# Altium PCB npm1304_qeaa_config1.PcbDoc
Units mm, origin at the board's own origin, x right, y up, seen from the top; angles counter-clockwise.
Board outline 16.75 x 14 mm, 4 copper layers (Top Layer, Mid-Layer 1, Mid-Layer 2, Bottom Layer), stack 1.592 mm thick; 22 components, 32 nets, 75 pads, 52 vias.
Unrouted connection lines stored in the file: 28.
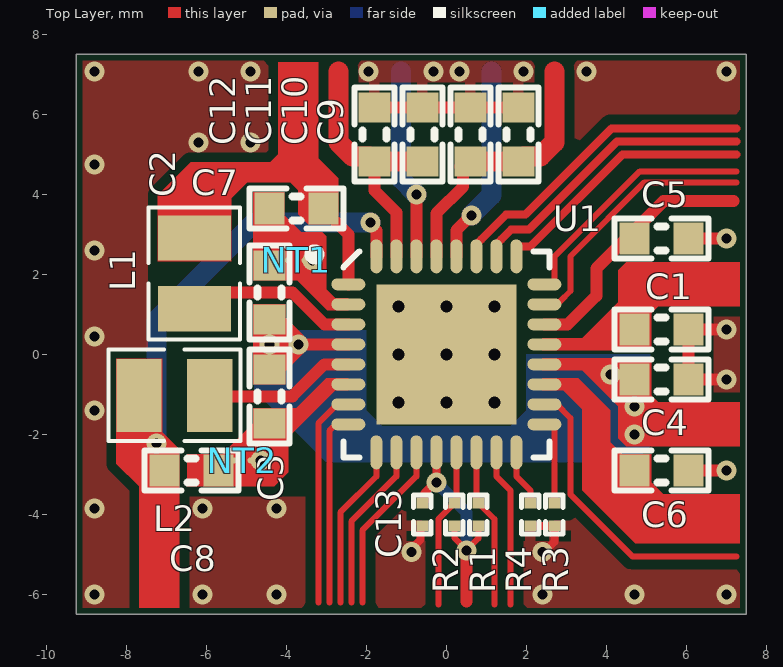
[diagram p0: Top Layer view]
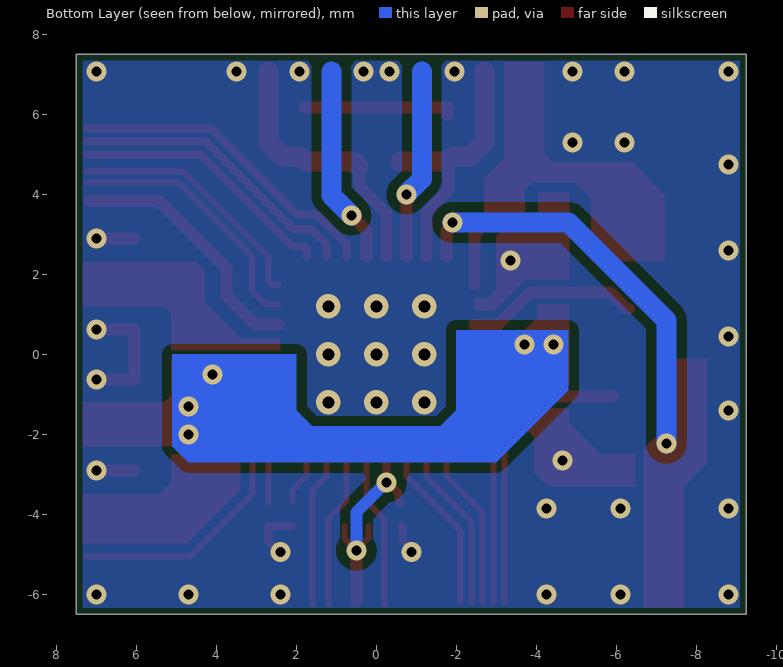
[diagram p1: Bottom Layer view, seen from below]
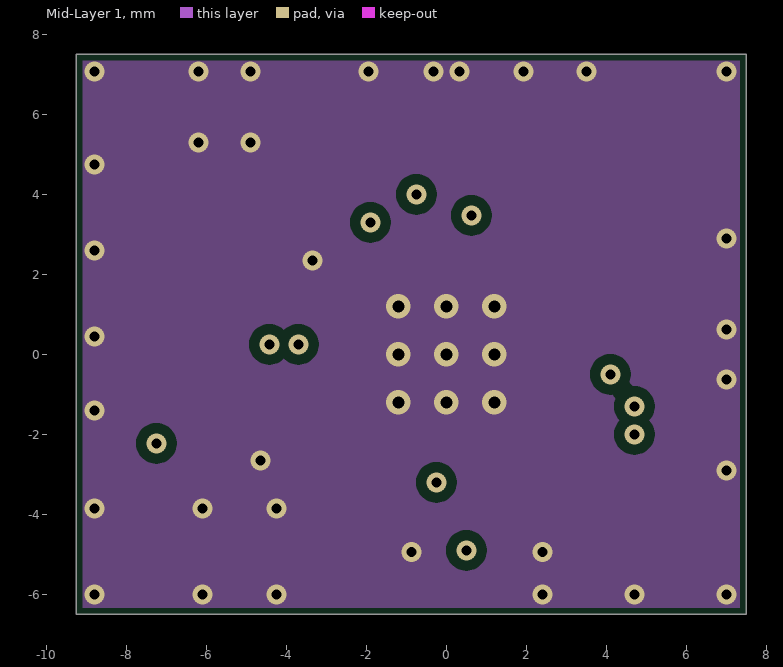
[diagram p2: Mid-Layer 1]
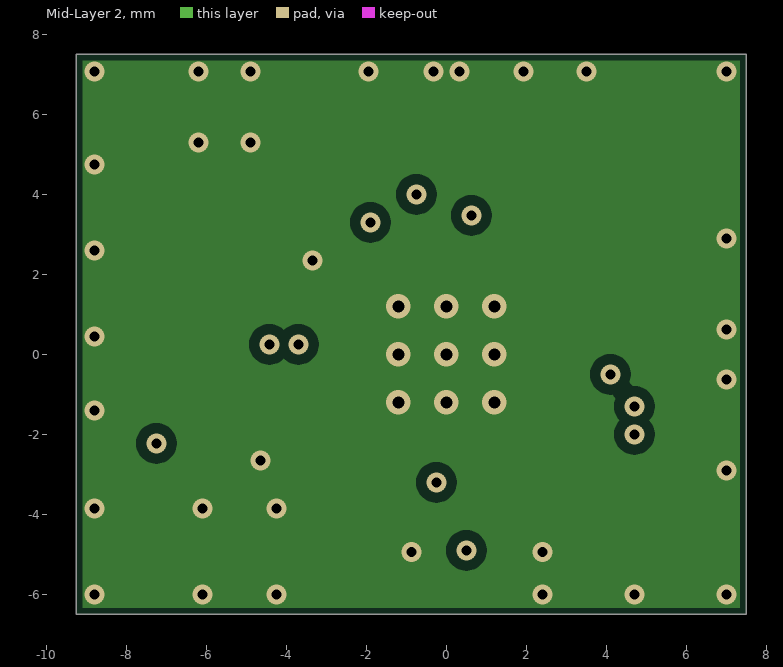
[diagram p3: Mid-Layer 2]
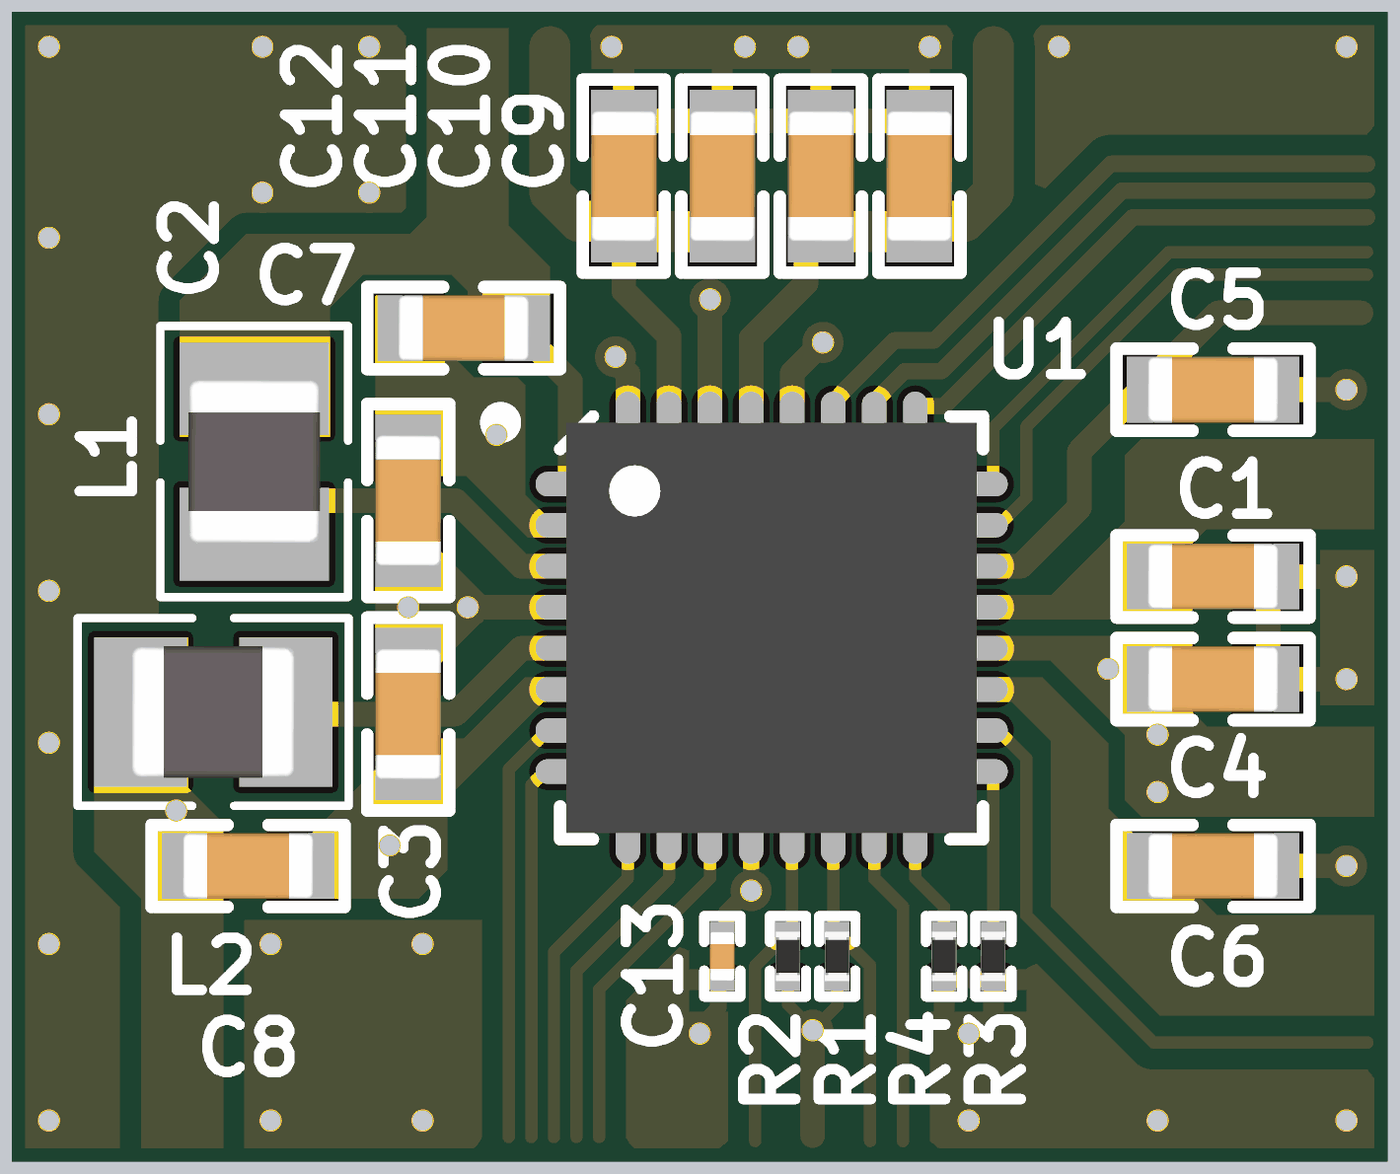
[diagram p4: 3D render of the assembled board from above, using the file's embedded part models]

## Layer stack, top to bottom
Top Solder: solder mask 0.0102, Solder Resist, Dk 3.5
Top Layer: signal copper 0.0356
Dielectric1: prepreg 0.075, FR-4, Dk 4.8
Mid-Layer 1: signal copper 0.0356
Dielectric2: core 1.3, FR-4, Dk 4.8
Mid-Layer 2: signal copper 0.0356
Dielectric 2: prepreg 0.075, FR-4, Dk 4.8
Bottom Layer: signal copper 0.0356
Bottom Solder: solder mask 0.0102, Solder Resist, Dk 3.5

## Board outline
-9.25,7.5 -9.25,-6.5 7.5,-6.5 7.5,7.5

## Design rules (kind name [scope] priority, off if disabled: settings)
BoardOutlineClearance [All] p1: gap=0.15 ignorepadtopadclearanceinfootprint=FALSE
Clearance Polygon_Clearance [(InNamedPolygon('Top_Layer-GND')) or (InNamedPolygon('Bottom_Layer-GND')) or (InNamedPolygon('Mid_Layer_1-GND')) or (InNamedPolygon('Mid_Layer_2-GND'))] p1: gap=0.254 ignorepadtopadclearanceinfootprint=FALSE except(0: Arc-Hole Track-Hole SMDPad-Hole THPad-Hole Via-Hole Fill-Hole Poly-Hole Region-Hole Text-Hole)
Clearance [All] p2: gap=0.125 ignorepadtopadclearanceinfootprint=FALSE
ComponentClearance [All] p1 off: gap=0.254 collisioncheckmode=3 verticalgap=0.254 showdistances=FALSE
DiffPairsRouting [All] p1: maxlimit=0.15 minlimit=0.127 mostfreqgap=0.15 toplayer_mingap=0.15 toplayer_minwidth=0.15 toplayer_maxwidth=0.15 toplayer_prefwidth=0.15 bottomlayer_mingap=0.15 bottomlayer_minwidth=0.15 bottomlayer_maxwidth=0.15 bottomlayer_prefwidth=0.15 impedanceprofiledriven=TRUE impedanceprofileid={DBD80B30-E3CF-4860-A6C7-45E32F93C55D} impedanceprofilevalue=90.000000 maxuncoupledlength=12.7
FabricationTestPointUsage TestPointUsage [All] p1: valid=0 allowmultiple=FALSE
FabricationTestpoint Testpoint [All] p1: side=3 testpointundercomponent=TRUE minsize=1.016 maxsize=2.54 preferedsize=1.524 minholesize=0 maxholesize=1.016 preferedholesize=0.813 testpointgrid=0.025 allowsidetop=TRUE allowsidebottom=TRUE usegrid=TRUE gridtolerance=0
Height [All] p1 off: minheight=0 maxheight=25.4 prefheight=12.7
HoleSize [All] p1: absolutevalues=TRUE maxlimit=5 minlimit=0.1 maxpercent=80.000 minpercent=20.000
MinimumAnnularRing [All] p1 off: minimumring=0.75
PolygonConnect PolygonConnect_GND [InNet('GND')] p1: thpad.connectstyle=Relief thpad.reliefconductorwidth=0.254 thpad.reliefentries=4 thpad.polygonreliefangle="90 Angle" thpad.airgapwidth=0.254 smdpad.connectstyle=Relief smdpad.reliefconductorwidth=0.254 smdpad.reliefentries=4 smdpad.polygonreliefangle="90 Angle" smdpad.airgapwidth=0.254 via.connectstyle=Direct via.reliefconductorwidth=0.254 via.reliefentries=4 via.polygonreliefangle="90 Angle" via.airgapwidth=0.254
PolygonConnect [All] p2: connectstyle=Direct reliefconductorwidth=0.254 reliefentries=4 polygonreliefangle="90 Angle" airgapwidth=0.254
RoutingVias [All] p1: holewidth=0.305 width=0.61 viastyle="Through Hole" minholewidth=0.305 minwidth=0.61 maxholewidth=0.711 maxwidth=1.27 useviatemplates=TRUE viatemplateguid#1={6F225C6A-EE86-4657-A426-C9A0349870D4} viatemplatename#1=v50h25m0mx0
ShortCircuit ShortCircuit_PVSS [InNet('PVSS1') or InNet('PVSS2') vs InNet('GND')] p1: allowed=TRUE
ShortCircuit [All] p2: allowed=FALSE
SilkToSolderMaskClearance SilkscreenOverComponentPads [IsPad] p1: minsilkscreentomaskgap=0.254 clearancetoexposedcopper=TRUE
SolderMaskExpansion SolderMaskExpansion_Vias [IsVia] p1: expansion=0.102 istentingtop=TRUE
SolderMaskExpansion [All] p2: expansion=0.076 istentingtop=FALSE
SupplyNets "Schematic Supply Nets_13" [InNet('VOUT2')] p1: voltage=0.000
SupplyNets "Schematic Supply Nets_12" [InNet('VOUTLDO2')] p2: voltage=0.000
SupplyNets "Schematic Supply Nets_11" [InNet('VSYS')] p3: voltage=0.000
SupplyNets "Schematic Supply Nets_10" [InNet('VBAT')] p4: voltage=0.000
SupplyNets "Schematic Supply Nets_9" [InNet('VOUT1')] p5: voltage=0.000
SupplyNets "Schematic Supply Nets_8" [InNet('VINLDO2')] p6: voltage=0.000
SupplyNets "Schematic Supply Nets_7" [InNet('PVSS1')] p7: voltage=0.000
SupplyNets "Schematic Supply Nets_6" [InNet('VBUSOUT')] p8: voltage=0.000
SupplyNets "Schematic Supply Nets_5" [InNet('VBUSIN')] p9: voltage=0.000
SupplyNets "Schematic Supply Nets_4" [InNet('VDDIO')] p10: voltage=0.000
SupplyNets "Schematic Supply Nets_3" [InNet('VINLDO1')] p11: voltage=0.000
SupplyNets "Schematic Supply Nets_2" [InNet('PVSS2')] p12: voltage=0.000
SupplyNets "Schematic Supply Nets_1" [InNet('GND')] p13: voltage=0.000
SupplyNets "Schematic Supply Nets" [InNet('VOUTLDO1')] p14: voltage=0.000
UnRoutedNet [All] p1: checkbadconnections=TRUE
Width [All] p1: maxlimit=2 minlimit=0.12 preferedwidth=0.3
21 further rules are at their usual default settings.

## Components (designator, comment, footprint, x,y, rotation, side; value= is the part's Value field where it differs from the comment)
C1 "1.0µF" CAPC1608X06L 5.375,0.625 r180 top
C2 "10µF" CAPC1608X06L -4.425,1.55 r270 top
C3 "10µF" CAPC1608X06L -4.425,-1.05 r90 top
C4 "10µF" CAPC1608X06L 5.375,-0.625 r180 top
C5 "1.0µF" CAPC1608X06L 5.375,2.9 r180 top
C6 "2.2µF" CAPC1608X06L 5.375,-2.9 r180 top
C7 "10µF" CAPC1608X06L -3.75,3.65 r0 top
C8 "10µF" CAPC1608X06L -6.375,-2.9 r180 top
C9 "10µF" CAPC1608X06L 1.8,5.5 r270 top
C10 "10µF" CAPC1608X06L 0.6,5.5 r270 top
C11 "10µF" CAPC1608X06L -0.6,5.5 r270 top
C12 "10µF" CAPC1608X06L -1.8,5.5 r270 top
C13 "100nF" CAPC0603X03L_C -0.6,-4 r270 top
L1 "2.2µH" INDC2016X10N -6.3,2.025 r270 top
L2 "2.2µH" INDC2016X10N -6.8,-1.025 r0 top
NT1 "Net tie" "2 PIN STARPOINT" -3.75,2.35 r0 top net-tie
NT2 "Net tie" "2 PIN STARPOINT" -5.1,-2.65 r0 top net-tie
R1 "10k" RESC0603X03L_C 0.8,-4 r270 top
R2 "10k" RESC0603X03L_C 0.2,-4 r270 top
R3 "47k" RESC0603X03L_C 2.7,-4 r270 top
R4 "150k" RESC0603X03L_C 2.1,-4 r270 top
U1 "nPM1304-QEAA" Nordic_QFN50P500X500X90-33N 0,0 r0 top locked

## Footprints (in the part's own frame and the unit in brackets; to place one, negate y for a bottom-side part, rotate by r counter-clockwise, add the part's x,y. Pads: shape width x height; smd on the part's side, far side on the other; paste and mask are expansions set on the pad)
"2 PIN STARPOINT" [mil]
  round 6 smd paste-196.85 mask-196.85: 1(8,0) 2(-8,0)
  Top Layer region: -8,-3 8,-3 8,3 -8,3
CAPC0603X03L_C [mm] "Chip Capacitor, 2-Leads, Body 0.6x0.3mm, IPC High Density"
  rect 0.27x0.3 smd mask+0.05: 1(-0.285,0) 2(0.285,0)
  silkscreen extent -0.49,-0.22 0.49,0.22, body extent -0.3,-0.15 0.3,0.15, height 0.3
CAPC1608X06L [mm] "Chip Capacitor, 2-Leads, Body 1.6x0.8mm, IPC High Density"
  rect 0.75x0.8 smd: 1(-0.675,0) 2(0.675,0)
  silkscreen extent -1.17,-0.5 1.17,0.5, body extent -0.8,-0.4 0.8,0.4, height 0.8
INDC2016X10N [mm] "Chip Inductor, 2-Leads, Body 2.00x1.60mm, IPC Medium Density"
  rect 1.13x1.82 smd: 1(-0.885,0) 2(0.885,0)
  silkscreen extent -1.65,-1.14 1.65,1.14, body extent -1,-0.8 1,0.8, height 1
Nordic_QFN50P500X500X90-33N [mm] "QFN32 5x5x0.85mm, 0.5mm pitch - Medium Density"
  oval 0.85x0.3 smd mask+0.076: 1(-2.45,1.75) 2(-2.45,1.25) 3(-2.45,0.75) 4(-2.45,0.25) 5(-2.45,-0.25) 6(-2.45,-0.75) 7(-2.45,-1.25) 8(-2.45,-1.75) 17(2.45,-1.75) 18(2.45,-1.25) 19(2.45,-0.75) 20(2.45,-0.25) 21(2.45,0.25) 22(2.45,0.75) 23(2.45,1.25) 24(2.45,1.75)
  oval 0.3x0.85 smd mask+0.076: 9(-1.75,-2.45) 10(-1.25,-2.45) 11(-0.75,-2.45) 12(-0.25,-2.45) 13(0.25,-2.45) 14(0.75,-2.45) 15(1.25,-2.45) 16(1.75,-2.45) 25(1.75,2.45) 26(1.25,2.45) 27(0.75,2.45) 28(0.25,2.45) 29(-0.25,2.45) 30(-0.75,2.45) 31(-1.25,2.45) 32(-1.75,2.45)
  rect 3.5x3.5 smd: 33(0,0)
  silkscreen extent -3.42,-2.57 2.57,2.62, body extent -2.5,-2.5 2.5,2.5, height 0.9
RESC0603X03L_C [mm] "Chip Resistor, 2-Leads, Body 0.6x0.3mm, IPC High Density"
  rect 0.27x0.3 smd: 1(-0.285,0) 2(0.285,0)
  silkscreen extent -0.49,-0.22 0.49,0.22, body extent -0.3,-0.15 0.3,0.15, height 0.23

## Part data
C1: library part C0603-1µ0-25V-X5R, "Capacitor, X5R, ±10%, 25V", Manufacturer=N.A., Part number NEMS=100200687
C2 C3 C4 C7 C8 C9 C10 C11 C12: library part C0603-10µ, "Capacitor, X5R, ±20%", Manufacturer=N.A., Part number IPS=00000007785, Part number NEMS=100200275
C5: library part C0603-1µ0-10V-X5R, "Capacitor, Ceramic, 1.0µF 10V X5R 0603,±10%", Manufacturer=N.A., Part number NEMS=100200528
C6: library part C0603-2.2µ-16V-X7R, "Capacitor, Ceramic, X7R, ±10%, 16V", Manufacturer="Taiyo Yuden", Manufacturer Part Number=EMK107BB7225KA-T, Part number IPS=N.A., Part number NEMS=100200439, Supplier Part Number 1=587-5835-2-ND
C13: library part C0201-100n, "Capacitor, X5R, ±10%, 100nF, 16V", Manufacturer=N.A., Part number IPS="00000001248, 00000002505", Part number NEMS=100200078, Part number Norautron=262071862
L1 L2: library part L0806-2µ2-2500mA-73mOhm-CIGT201610EH2R2MNE, "Inductor, Irms=2.5A, Isat=2.9A, ±20%, DCR=73mΩ", Manufacturer="Samsung Electro-Mechanics America", Manufacturer Part Number=CIGT201610EH2R2MNE, Part number IPS=N.A., Part number NEMS=100300400, Part number Norautron=26521789, Supplier Part Number 1=1276-6901-1-ND
NT1 NT2: library part "2 pin starpoint", "Starpoint", Manufacturer=N.A., Part number NEMS=100500603
R1 R2: library part R0201-10k, "Resistor, ±1%, 0.05W", Manufacturer=N.A., Part number IPS=00000001255, Part number NEMS=100100065, Part number Norautron=26107101
R3: library part R0201-47k, "Resistor, ±1%, 0.05W", Manufacturer=N.A., Part number IPS=00000001423, Part number NEMS=100100076
R4: library part R0201-150k, "Resistor, ±1%, 0.05W", Manufacturer=N.A., Part number IPS=00000001422, Part number NEMS=100100082
U1: "Li-Ion/Li-Polymer USB-C battery charger with high efficiency buck regulators, LDOs or load switches, LED drivers, TWI and VBUSOUT", Manufacturer="Nordic Semiconductor", Part number IPS=N.A., Part number NEMS=102000396

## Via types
v1: diameter 0.5, hole 0.25, Top Layer to Bottom Layer, tented both sides, 43 vias
v2: diameter 0.61, hole 0.305, Top Layer to Bottom Layer, tented both sides, 9 vias

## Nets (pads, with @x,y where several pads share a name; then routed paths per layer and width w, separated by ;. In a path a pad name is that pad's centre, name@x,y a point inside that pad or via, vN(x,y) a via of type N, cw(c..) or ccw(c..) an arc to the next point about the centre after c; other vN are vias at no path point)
CC1: U1.23 | length 6.6
  Top Layer w0.15: U1.23 2.766,1.25 2.841,1.325 2.846,1.325 3.104,1.583 3.104,2.453 4.951,4.3 7.25,4.3
CC2: U1.24 | length 6.3
  Top Layer w0.15: U1.24 2.631,1.75 2.7,1.819 2.7,2.438 4.837,4.575 7.25,4.575
GND: C1.1 C4.1 C5.1 C6.1 C9.1 C10.1 C11.1 C12.1 C13.2 NT1.1 NT2.1 R3.2 R4.2 U1.33 | length 10.4
  Top Layer w0.15: NT2.1 v1(-4.65,-2.65) ; NT1.1 v1(-3.35,2.35)
  Top Layer w0.2: v1(-0.875,-4.941) -0.875,-4.859 -0.65,-4.634 -0.65,-4.315 C13.2@-0.627,-4.292 ; R4.2 R3.2@2.585,-4.285 ; v1(2.4,-4.941) 2.444,-4.941 2.7,-4.685 R3.2
  Top Layer w0.3: C12.1@-1.8,6 C12.1@-1.775,5.975 ; C12.1 C10.1 C9.1 ; C6.1 v1@6.9,-2.9 ; C4.1 C1.1 v1@6.8,0.625 ; C5.1 v1@6.8,2.9 ; C4.1@6.125,-0.625 v1@6.8,-0.625
  other v1: -8.8,-6 -6.1,-6 -4.25,-6 2.4,-6 4.7,-6 7,-6 -8.8,-3.85 -6.1,-3.85 -4.25,-3.85 7,-2.9 -8.8,-1.4 7,-0.625 -8.8,0.45 7,0.625 -8.8,2.6 7,2.9 -8.8,4.75 -6.2,5.3 -4.9,5.3 -8.8,7.075 -6.2,7.075 -4.9,7.075 -1.95,7.075 -0.325,7.075 0.325,7.075 1.925,7.075 3.5,7.075 7,7.075
  other v2: -1.2,-1.2 0,-1.2 1.2,-1.2 -1.2,0 0,0 1.2,0 -1.2,1.2 0,1.2 1.2,1.2
GPIO0: U1.7 | length 5.4
  Top Layer w0.15: -3.2,-6.2 -3.2,-1.725 -2.725,-1.25 U1.7
GPIO1: U1.8 | length 4.8
  Top Layer w0.15: -2.925,-6.2 -2.925,-1.913 -2.762,-1.75 U1.8
GPIO2: U1.9 | length 4.1
  Top Layer w0.15: -2.65,-6.2 -2.65,-3.95 -1.753,-3.053 -1.753,-2.453 U1.9
GPIO3: U1.10 | length 4.2
  Top Layer w0.15: -2.375,-6.2 -2.375,-4.175 -1.25,-3.05 U1.10
GPIO4: U1.11 | length 4.3
  Top Layer w0.15: -2.1,-6.2 -2.1,-4.4 -0.75,-3.05 U1.11
LED0: U1.25 | length 6.7
  Top Layer w0.2: U1.25 1.75,2.652 1.796,2.698 2.098,2.698 4.4,5 7.25,5
LED1: U1.26 | length 7.4
  Top Layer w0.2: U1.26 1.25,2.752 1.375,2.877 1.375,2.88 1.62,3.125 2.065,3.125 4.265,5.325 7.25,5.325
LED2: U1.27 | length 8
  Top Layer w0.2: U1.27 0.75,2.752 0.875,2.877 0.875,2.88 1.495,3.5 1.981,3.5 4.131,5.65 7.25,5.65
NTC: U1.18 | length 7.5
  Top Layer w0.15: U1.18 2.761,-1.25 3.1,-1.589 3.1,-3.5 4.65,-5.05 7.255,-5.05
PVSS1: C2.1 C7.1 NT1.2 U1.2 | length 0.5
  Top Layer w0.15: C2.1 -4.3,2.35 NT1.2
PVSS2: C3.1 C8.1 NT2.2 U1.6 | length 0.5
  Top Layer w0.15: C8.1 -5.45,-2.65 NT2.2
SCL: R1.1 U1.14 | length 4
  Top Layer w0.15: U1.14 0.75,-3.665 R1.1 0.815,-3.715 0.875,-3.775 0.875,-3.79 1.2,-4.115 1.2,-6.25
SDA: R2.1 U1.13 | length 4
  Top Layer w0.15: -0.2,-6.25 -0.2,-4.117 0.125,-3.792 0.125,-3.775 0.22,-3.68 0.25,-3.68 U1.13
SHPHLD: U1.15 | length 3.9
  Top Layer w0.15: U1.15 1.25,-3.05 1.6,-3.4 1.6,-6.25
SW1: L1.2 U1.3 | length 4.4
  Top Layer w0.3: L1.2 -6.25,1.14 -5.84,1.55 -3.85,1.55 -3.05,0.75 U1.3
SW2: L2.2 U1.5 | length 3.8
  Top Layer w0.3: L2.2 -5.89,-1.05 -3.85,-1.05 -3.05,-0.25 U1.5
VBAT: C6.2 U1.19
VBUSIN: C1.2 U1.21
VBUSOUT: C5.2 U1.22 | length 6.4
  Top Layer w0.3: U1.22 3.033,0.75 3.748,1.465 3.748,2.148 5.434,3.834 7.175,3.834
VDDIO: C13.1 R1.2 R2.2 U1.12 | length 6.2
  Top Layer w0.15: R2.2 0.2,-4.586 v1@0.45,-4.836 ; v1@0.5,-4.786 v1(0.5,-4.9) 0.8,-4.6 R1.2
  Top Layer w0.2: C13.1 -0.585,-3.715 -0.55,-3.68 -0.55,-3.467 -0.283,-3.2 v1(-0.25,-3.2) -0.25,-3 U1.12
  Top Layer w0.3: 0.5,-6.182 v1(0.5,-4.9)
  Bottom Layer w0.3: v1(-0.25,-3.2) 0.5,-3.95 v1(0.5,-4.9)
VINLDO1: U1.28 | length 5
  Top Layer w0.3: U1.28 0.25,3.1 v1(0.625,3.475)
  Bottom Layer w0.5: v1(0.625,3.475) 1.125,3.975 1.125,7.075
VINLDO2: U1.30 | length 4.8
  Top Layer w0.3: U1.30 v1(-0.75,4)
  Bottom Layer w0.5: -1.135,7.075 -1.135,4.385 v1(-0.75,4)
VOUT1: C7.2 L1.1 U1.1 | length 2.1
  Top Layer w0.3: C7.2@-3.075,3.625 -2.45,3 U1.1
VOUT2: C8.2 L2.1 U1.32 | length 13.3
  Top Layer w0.3: L2.1 L2.1@-7.275,-1.435 ; v1(-7.25,-2.225) -7.27,-2.205 -7.27,-1.44 L2.1@-7.275,-1.435 ; C8.2 -7.275,-2.675 L2.1@-7.275,-1.435 ; v1(-1.9,3.3) -1.9,3.246 -1.75,3.096 U1.32
  Bottom Layer w0.5: v1(-7.25,-2.225) -7.25,0.85 -4.8,3.3 v1(-1.9,3.3)
VOUTLDO1: C9.2 C10.2 U1.29 | length 7
  Top Layer w0.3: U1.29 -0.25,3.525 0.419,4.194 0.419,4.669 C10.2@0.45,4.7
  Top Layer w0.5: C10.2@0.45,4.7 0.575,4.825 C10.2 C9.2 ; 2.7,7.075 2.7,5.3 2.35,4.95 C9.2@1.925,4.95 ; C9.2 C9.2@1.925,4.95 ; C9.2 C9.2@1.925,4.95
VOUTLDO2: C11.2 C12.2 U1.31 | length 6.7
  Top Layer w0.3: C12.2 -1.8,4.1 -1.25,3.55 U1.31
  Top Layer w0.5: -2.7,7.075 -2.7,5.3 -2.35,4.95 -1.925,4.95 C12.2 C11.2
VSET1: R3.1 U1.17 | length 2.2
  Top Layer w0.15: U1.17 2.631,-1.75 2.7,-1.819 R3.1
VSET2: R4.1 U1.16 | length 1.4
  Top Layer w0.15: U1.16 1.75,-3.05 2.1,-3.4 R4.1@2.1,-3.684
VSYS: C2.2 C3.2 C4.2 U1.4 U1.20 | length 1.1
  Top Layer w0.3: v1@-3.596,0.25 U1.4
  other v1: 4.7,-2 4.7,-1.3 4.1,-0.5 -4.425,0.25 -3.7,0.25

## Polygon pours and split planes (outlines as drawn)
GND on Mid-Layer 1 "Mid_Layer_1-GND" (solid, remove dead copper, pour order 24): -9.25,-6.5 7.5,-6.5 7.5,7.5 -9.25,7.5
GND on Mid-Layer 2 "Mid_Layer_2-GND" (solid, remove dead copper, pour order 25): -9.25,-6.5 7.5,-6.5 7.5,7.5 -9.25,7.5
GND on Bottom Layer "Bottom_Layer-GND" (solid, remove dead copper, pour order 26): -9.25,-6.5 7.5,-6.5 7.5,7.5 -9.25,7.5
GND on Top Layer "Top_Layer-GND" (solid, remove dead copper, pour order 21): -9.25,-6.5 7.5,-6.5 7.5,7.5 -9.25,7.5

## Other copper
Top Layer:
  region net VOUT1: -6.593,4.6 -6.393,4.8 -4.4,4.8 -4.2,5 -4.2,7.3 -3.2,7.3 -3.2,4.9 -2.7,4.4 -2.7,3.25 -3.45,3.25 -3.704,3.504 -3.704,4.096 -3.7,4.1 -3.9,4.3 -6.593,4.3
  region net VOUT2: -6.675,-2.375 -6.675,-6.338 -7.679,-6.338 -7.679,-2.375
  region net VBUSIN: 5.125,0.1 5.125,1.025 5.3,1.2 7.338,1.2 7.338,2.3 4.5,2.3 4.3,2.1 4.3,1.3 3.4,0.4 2.4,0.4 2.4,0.1
  region net VSYS: 5.125,-0.1 5.125,-1.025 5.3,-1.2 7.338,-1.2 7.338,-2.3 4.5,-2.3 4.3,-2.1 4.3,-1.3 3.4,-0.4 2.4,-0.4 2.4,-0.1
  region net VBAT: 2.4,-0.9 2.925,-0.9 3.4,-1.375 3.4,-3.4 4.725,-4.725 7.338,-4.725 7.338,-3.5 5.425,-3.5 5.125,-3.2 5.125,-2.5 4.4,-2.5 4.1,-2.2 4.1,-1.4 3.3,-0.6 2.4,-0.6
  region net PVSS2: -2.45,-0.6 -3,-0.6 -3.75,-1.35 -4.825,-1.35 -4.825,-1.725 -5.6,-2.5 -6.475,-2.5 -6.475,-3.3 -4.3,-3.3 -3.95,-2.95 -3.95,-2.075 -2.775,-0.9 -2.45,-0.9
  pour cut-out: -1.85,1.85 1.85,1.85 1.85,-1.85 -1.85,-1.85
  pour cut-out: -6.5,-2.766 -6.5,-3.555 -3.138,-3.555 -3.138,-2.766
  region net VOUT1: -4.972,4.303 -5.375,3.9 -5.375,2.325 -7.21,2.325 -7.21,3.983 -6.593,4.6 -4.972,4.6
  region net VOUT2: -7.1,-0.115 -7.1,-1.95 -6.675,-2.375 -6.675,-3.3 -7.679,-3.3 -8.25,-2.729 -8.25,-0.115
  region net PVSS1: -4.825,4.05 -4.05,4.05 -4.05,3.475 -3.625,3.05 -3.1,3.05 -3,2.95 -3,1.625 -2.775,1.4 -2.45,1.4 -2.45,1.1 -2.975,1.1 -3.725,1.85 -4.825,1.85
  pour cut-out: -7.464,2.325 -7.464,-0.115 -5.375,-0.115 -5.375,2.325
  region net VSYS: -3.5,0.4 -4.025,0.925 -4.025,1.25 -4.825,1.25 -4.825,-0.75 -4.025,-0.75 -4.025,-0.425 -3.5,0.1
Bottom Layer:
  region net VSYS: -4.8,0.6 -4.8,-0.9 -3,-2.7 4.7,-2.7 5.1,-2.3 5.1,0 2,0 2,-1.4 1.6,-1.8 -1.6,-1.8 -2,-1.4 -2,0.6

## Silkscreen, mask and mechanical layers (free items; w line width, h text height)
Board Outline:
  the board outline again, w0.2

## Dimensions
7.5,-6.5 to 7.5,7.5 on Dimension
-9.25,-6.5 to 7.5,-6.5 on Dimension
